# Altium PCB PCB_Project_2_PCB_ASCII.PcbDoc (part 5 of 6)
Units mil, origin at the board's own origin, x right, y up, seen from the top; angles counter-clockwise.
Board outline 3900 x 7800 mil, 6 copper layers (Top Layer, GND 1, Signal, Power, GND 2, Bottom Layer), stack 62.1 mil thick; 636 components, 334 nets, 1830 pads, 1401 vias.
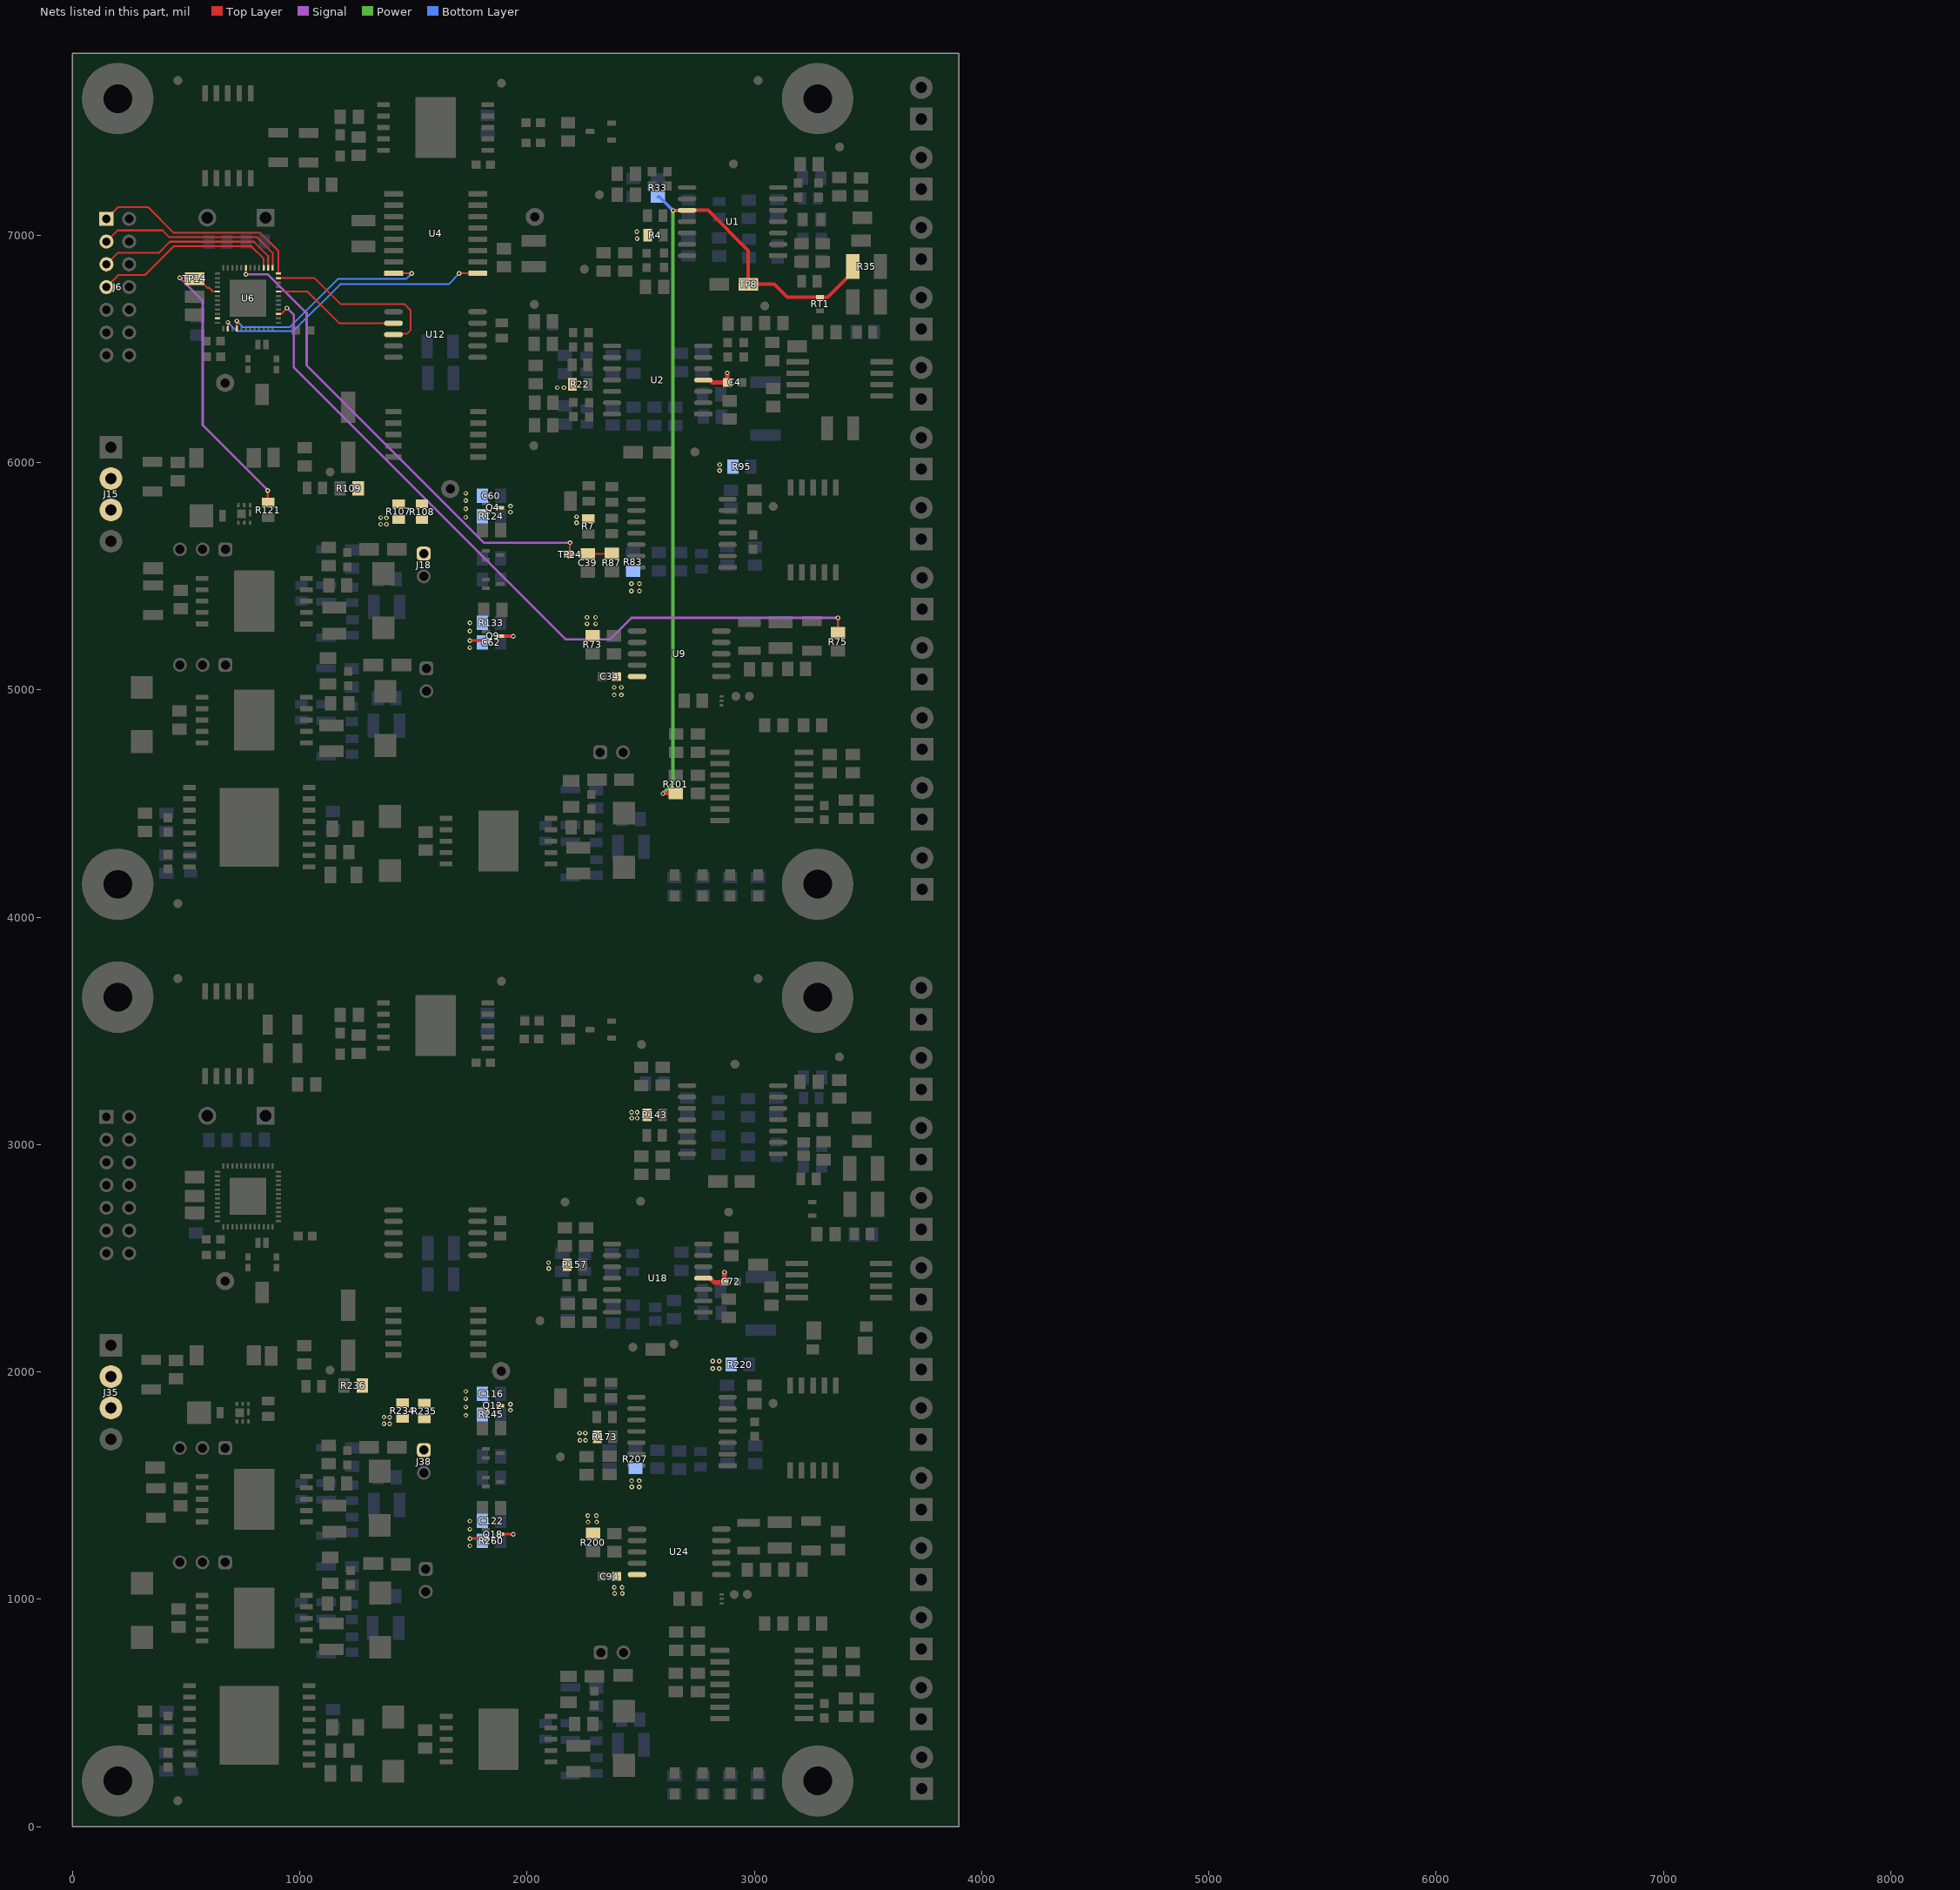
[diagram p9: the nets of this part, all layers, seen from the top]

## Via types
v1: diameter 20, hole 10, Top Layer to Bottom Layer, tented both sides, 1161 vias
v2: diameter 19.68, hole 7.87, Top Layer to Bottom Layer, 240 vias

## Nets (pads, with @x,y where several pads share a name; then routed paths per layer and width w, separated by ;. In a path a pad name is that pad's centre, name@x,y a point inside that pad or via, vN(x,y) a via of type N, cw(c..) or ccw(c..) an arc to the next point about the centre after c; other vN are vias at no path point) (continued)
"PWM for Boost": R121.2 TP14.1 U6.29 | length 1346.1
  Top Layer w8: v1(472.21,6812.48) TP14.1@536.72,6812.48 ; TP14.1@538.75,6807.64 548.11,6817.01 554.25,6810.87 554.25,6807.89 594.18,6767.96 602.45,6767.96 618.57,6751.84 U6.29@639.25,6751.84 ; R121.2@859.56,5826.44 v1(859.56,5876.24)
  Signal w10: v1(472.21,6812.48) 573.48,6711.22 573.48,6164.07 v1@862.25,5875.31
"PWM for Current Source": R75.1 U6.3 | length 3316.4
  Top Layer w8: U6.3@906.97,6653.42 907.69,6654.14 920.35,6654.14 944.33,6678.12 v1(944.33,6679.12) ; v1(3368,5316.59) 3368.41,5316.18 R75.1@3368.41,5250.84
  Signal w10: v1(944.33,6679.12) 975.12,6648.33 975.12,6417.77 2171.38,5221.51 2365.01,5221.51 2460.09,5316.59 v1(3368,5316.59)
"Servo Amp": C39.1 R87.2 TP24.1 U6.19 | length 2320.3
  Top Layer w8: U6.19@763.27,6856.18 763.35,6856.09 763.35,6827.42 v1(763.43,6827.34) ; v1@2189.25,5651.68 v1(2189.25,5647.41) TP24.1@2189.25,5595.74 2270.36,5595.74 2272.66,5598.04 2372.32,5598.04 R87.2@2373.79,5599.5
  Signal w10: v1@764.43,6827.64 859.66,6827.64 1030.94,6656.36 1030.94,6426.37 1810.31,5647 v1@2190,5647
SPI_CLK_3wire: U6.11 U12.8 | length 811
  Top Layer w7.5: U6.11@906.97,6810.9 1065.99,6810.9 1179.89,6697 1460.72,6697 1488.18,6669.54 1488.18,6581.18 1472.5,6565.5 1415.98,6565.5 U12.8@1413,6562.51
SPI_CLK_4wire: U4.16 U6.40 | length 984.7
  Top Layer w8: U6.40@723.73,6588.62 v1@723.73,6616.39 ; U4.16@1414.19,6831.75 v1@1493.41,6831.75
  Bottom Layer w7.5: v1(724,6622) 750.37,6595.63 956.66,6595.63 1169.03,6808 1470.03,6808 v1(1493.22,6831.19)
SPI_CS1: U4.1 U6.38 | length 1247.8
  Top Layer w8: v1(684.14,6616.44) 684.33,6616.25 684.33,6588.65 U6.38@684.53,6588.46 ; v1@1702.74,6831.57 U4.1@1783.7,6831.57
  Bottom Layer w7.5: v1(684.14,6616.44) 722.81,6577.78 972.61,6577.78 1178.94,6784.1 1655.28,6784.1 v1(1701.99,6830.81)
SPI_CS2: U6.8 U12.7 | length 563.7
  Top Layer w7.5: U6.8@906.97,6751.84 1034.22,6751.84 1173.55,6612.51 U12.7@1413,6612.51
SPI_CS3: U6.35
TCk: J6.7 U6.15 | length 829.1
  Top Layer w8: J6.7@150,6771.53 203.09,6824.62 320.19,6824.62 446.55,6950.98 787.4,6950.98 842.01,6896.37 U6.15@842.01,6856.18
TDI: J6.3 U6.13 | length 858.3
  Top Layer w8: J6.3@150,6971.53 199.14,7020.67 397.07,7020.67 427.23,6990.51 812.65,6990.51 881.38,6921.78 U6.13@881.38,6856.18
TDO: J6.1 U6.12 | length 957.7
  Top Layer w8: J6.1@150,7071.53 201.7,7123.23 332.99,7123.23 446.38,7009.84 826.88,7009.84 906.97,6929.75 U6.12@906.97,6830.58
"Temp Voltage": R33.1 R35.1 R101.2 RT1.2 TP8.1 U1.10 | length 3839.6
  Top Layer w10: R101.2@2654.22,4543.55 R101.2@2655.24,4544.57
  Top Layer w15: v1(2598.17,4543.55) R101.2@2654.22,4543.55 ; v1(2642.9,7108) U1.10@2707,7108 ; U1.10@2704.48,7109.19 2796.41,7109.19 2973.9,6931.7 TP8.1@2973.9,6784.12 3087.9,6784.12 3145.01,6727 RT1.2@3289,6727 3323.97,6727 3432.88,6835.91 R35.1@3432.88,6861.5
  Power w15: v1(2598.17,4543.55) 2642.9,4588.28 v1(2642.9,7108)
  Bottom Layer w15: R33.1@2577,7168.11 2583.5,7168.11 2642.9,7108.72 v1(2642.9,7108)
TMS: J6.5 U6.14 | length 830.5
  Top Layer w8: J6.5@150,6871.53 199.86,6921.39 380.52,6921.39 429.88,6970.75 798.73,6970.75 861.69,6907.79 U6.14@861.69,6856.18
Vcc: C4.2 C34.1 Q4.3 R73.2 R83.2 R95.2 U2.4 U9.10 | length 153.5
  Top Layer w20: U2.4@2775.45,6362.45 2805.58,6362.45 2816.03,6352 C4.2@2882.5,6352 2881.15,6353.35 v1(2881.15,6393.53)
  other v1: 2383.76,4977.57 2415.64,4977.57 2383.76,5010.35 2415.64,5010.35 2264,5290.09 2302,5290.09 2264,5318.53 2302,5318.53 2459.5,5434.63 2495.03,5434.63 2459.5,5466.58 2495.03,5466.58 1927.65,5781.6 1927.65,5808.04 2848.1,5964.52 2848.1,5990.07
Vcc(m): C72.2 C94.1 Q12.3 R200.2 R207.2 R220.2 U18.4 U24.10 | length 144.3
  Top Layer w20: U18.4@2775.84,2412.5 2805.97,2412.5 2824.47,2394 C72.2@2870,2394 ; v1(2868.5,2438.5) 2868.5,2399.18 C72.2@2870.7,2396.98
  other v1: 2385.58,1025.79 2419.93,1025.79 2384.21,1052.74 2418.57,1052.74 2268.84,1340.1 2306.84,1340.1 2267.51,1368.05 2305.51,1368.05 2461.13,1494.14 2493.74,1494.14 2460.44,1521.78 2493.65,1521.78 1927.65,1831.6 1927.65,1858.04 2817,2015 2846,2015 2817,2047 2846,2047
Vcc(m,x): J35.2 R234.1
  other v1: 1371.15,1771.93 1396.48,1771.93 1396.48,1800.21 1371.15,1800.97
Vcc(m,y): J38.1 R235.1
Vcc(mz): C116.1 Q12.2 R234.2 R235.2 R236.2 R245.2
  other v1: 1731,1808.84 1731,1845.92 1731,1882.2 1731,1914.19
Vcc(x): J15.2 R107.1
  other v1: 1356.59,5728.18 1381.92,5728.18 1381.92,5756.46 1356.59,5757.23
Vcc(y): J18.1 R108.1
Vcc(z): C60.1 Q4.2 R107.2 R108.2 R109.2 R124.2
  other v1: 1731,5758.84 1731,5795.92 1731,5832.2 1731,5864.19
Vee: Q9.3 R4.1 R7.1 R22.1 | length 57.7
  Top Layer w10: Q9.3@1882.44,5236.31 Q9.3@1882.75,5236 ; v1@1939.49,5236 v1(1939.88,5235.61)
  Top Layer w15: Q9.3@1882.75,5236 v1@1939.49,5236
  other v1: 2218.2,5734.8 2218.2,5761.07 2133.65,6329 2162.72,6329 2484.77,6984.53 2483.52,7014.5
Vee(m): Q18.3 R143.1 R157.1 R173.1 | length 55.8
  Top Layer w12: Q18.3@1882.44,1286.31 v1@1938.28,1286.31
  other v1: 1939.88,1285.61 2233,1699 2258,1699 2232,1731 2257,1731 2096,2455 2095,2481 2461,3116.19 2485,3116 2460.5,3142 2485,3142
Vee(mx): C122.2 J35.3 Q18.2 R260.1 | length 70.6
  Top Layer w12: v1@1747.18,1267.18 Q18.2@1817.74,1267.18
  other v1: 1748.89,1235 1748.89,1266.63 1748.89,1308.11 1748.89,1344.26
Vee(x): C62.2 J15.3 Q9.2 R133.1 | length 70.6
  Top Layer w12: v1(1748.89,5216.63) Q9.2@1819.44,5216.63
  other v1: 1748.89,5185 1748.89,5258.11 1748.89,5294.26
pads on no net: FID1.1 FID2.1 FID3.1 FID4.1 FID5.1 FID6.1 FID7.1 FID8.1 FID9.1 FID10.1 FID11.1 FID12.1 H1.1 H2.1 H3.1 H4.1 H5.1 H6.1 H7.1 H8.1 H9.0 H10.0 H11.0 H12.0 H13.0 H14.0 H15.0 H16.0 H17.0 H18.0 H19.0 H20.0 J6.2 J6.6 J6.10 J6.12 J6.13 J6.14 J27.2 J27.6 J27.10 J27.12 J27.13 J27.14 LBL1.0 Q2.1@2855.63,4972.34 Q2.2@2855.63,4951.67 Q2.3@2855.63,4931 Q3.0 Q11.1@2856.51,1022.55 Q11.2@2856.51,1001.88 Q11.3@2856.51,981.21 Q14.0 U6.1 U6.4 U6.5 U6.6 U6.7 U6.9 U6.10 U6.16 U6.17 U6.18 U6.25 U6.26 U6.27 U6.33 U6.34 U6.39 U6.42 U6.43 U6.49@719.17,6668.38 U6.49@719.17,6722.32 U6.49@719.17,6776.25 U6.49@773.11,6668.38 U6.49@773.11,6722.32 U6.49@773.11,6776.25 U6.49@827.04,6668.38 U6.49@827.04,6722.32 U6.49@827.04,6776.25 U7.7 U8.11@1530.37,7359.98 U8.11@1530.37,7405.25 U8.11@1530.37,7450.53 U8.11@1530.37,7495.81 U8.11@1530.37,7541.08 U8.11@1530.37,7586.36 U8.11@1575.64,7359.98 U8.11@1575.64,7405.25 U8.11@1575.64,7450.53 U8.11@1575.64,7495.81 U8.11@1575.64,7541.08 U8.11@1575.64,7586.36 U8.11@1620.92,7359.98 U8.11@1620.92,7405.25 U8.11@1620.92,7450.53 U8.11@1620.92,7495.81 U8.11@1620.92,7541.08 U8.11@1620.92,7586.36 U8.11@1666.19,7359.98 U8.11@1666.19,7405.25 U8.11@1666.19,7450.53 U8.11@1666.19,7495.81 U8.11@1666.19,7541.08 U8.11@1666.19,7586.36 U9.5 U9.6 U12.2 U12.3 U12.5 U12.6 U13.5 U13.11@732.16,4753.74 U13.11@732.16,4799.01 U13.11@732.16,4844.29 U13.11@732.16,4889.56 U13.11@732.16,4934.84 U13.11@732.16,4980.11 U13.11@777.43,4753.74 U13.11@777.43,4799.01 U13.11@777.43,4844.29 U13.11@777.43,4889.56 U13.11@777.43,4934.84 U13.11@777.43,4980.11 U13.11@822.71,4753.74 U13.11@822.71,4799.01 U13.11@822.71,4844.29 U13.11@822.71,4889.56 U13.11@822.71,4934.84 U13.11@822.71,4980.11 U13.11@867.99,4753.74 U13.11@867.99,4799.01 U13.11@867.99,4844.29 U13.11@867.99,4889.56 U13.11@867.99,4934.84 U13.11@867.99,4980.11 U15.5 U15.11@732.88,5276.9 U15.11@732.88,5322.17 U15.11@732.88,5367.45 U15.11@732.88,5412.72 U15.11@732.88,5458 U15.11@732.88,5503.28 U15.11@778.15,5276.9 U15.11@778.15,5322.17 U15.11@778.15,5367.45 U15.11@778.15,5412.72 U15.11@778.15,5458 U15.11@778.15,5503.28 U15.11@823.43,5276.9 U15.11@823.43,5322.17 U15.11@823.43,5367.45 U15.11@823.43,5412.72 U15.11@823.43,5458 U15.11@823.43,5503.28 U15.11@868.7,5276.9 U15.11@868.7,5322.17 U15.11@868.7,5367.45 U15.11@868.7,5412.72 U15.11@868.7,5458 U15.11@868.7,5503.28 U16.5 U16.11@1807,4221.49 U16.11@1807,4266.77 U16.11@1807,4312.04 U16.11@1807,4357.32 U16.11@1807,4402.59 U16.11@1807,4447.87 U16.11@1852.28,4221.49 U16.11@1852.28,4266.77 U16.11@1852.28,4312.04 U16.11@1852.28,4357.32 U16.11@1852.28,4402.59 U16.11@1852.28,4447.87 U16.11@1897.56,4221.49 U16.11@1897.56,4266.77 U16.11@1897.56,4312.04 U16.11@1897.56,4357.32 U16.11@1897.56,4402.59 U16.11@1897.56,4447.87 U16.11@1942.83,4221.49 U16.11@1942.83,4266.77 U16.11@1942.83,4312.04 U16.11@1942.83,4357.32 U16.11@1942.83,4402.59 U16.11@1942.83,4447.87 U20.9 U20.10 U20.25 U20.26 U20.27 U20.33 U20.34 U20.39 U20.42 U20.43 U20.49@719.17,2718.38 U20.49@719.17,2772.32 U20.49@719.17,2826.25 U20.49@773.11,2718.38 U20.49@773.11,2772.32 U20.49@773.11,2826.25 U20.49@827.04,2718.38 U20.49@827.04,2772.32 U20.49@827.04,2826.25 U22.7 U23.11@1530.37,3409.98 U23.11@1530.37,3455.25 U23.11@1530.37,3500.53 U23.11@1530.37,3545.8 U23.11@1530.37,3591.08 U23.11@1530.37,3636.36 U23.11@1575.64,3409.98 U23.11@1575.64,3455.25 U23.11@1575.64,3500.53 U23.11@1575.64,3545.8 U23.11@1575.64,3591.08 U23.11@1575.64,3636.36 U23.11@1620.92,3409.98 U23.11@1620.92,3455.25 U23.11@1620.92,3500.53 U23.11@1620.92,3545.8 U23.11@1620.92,3591.08 U23.11@1620.92,3636.36 U23.11@1666.19,3409.98 U23.11@1666.19,3455.25 U23.11@1666.19,3500.53 U23.11@1666.19,3545.8 U23.11@1666.19,3591.08 U23.11@1666.19,3636.36 U24.5 U24.6 U27.2 U27.3 U27.5 U27.6 U28.5 U28.11@732.16,803.74 U28.11@732.16,849.01 U28.11@732.16,894.29 U28.11@732.16,939.56 U28.11@732.16,984.84 U28.11@732.16,1030.11 U28.11@777.43,803.74 U28.11@777.43,849.01 U28.11@777.43,894.29 U28.11@777.43,939.56 U28.11@777.43,984.84 U28.11@777.43,1030.11 U28.11@822.71,803.74 U28.11@822.71,849.01 U28.11@822.71,894.29 U28.11@822.71,939.56 U28.11@822.71,984.84 U28.11@822.71,1030.11 U28.11@867.99,803.74 U28.11@867.99,849.01 U28.11@867.99,894.29 U28.11@867.99,939.56 U28.11@867.99,984.84 U28.11@867.99,1030.11 U30.5 U30.11@732.88,1326.9 U30.11@732.88,1372.17 U30.11@732.88,1417.45 U30.11@732.88,1462.72 U30.11@732.88,1508 U30.11@732.88,1553.28 U30.11@778.15,1326.9 U30.11@778.15,1372.17 U30.11@778.15,1417.45 U30.11@778.15,1462.72 U30.11@778.15,1508 U30.11@778.15,1553.28 U30.11@823.43,1326.9 U30.11@823.43,1372.17 U30.11@823.43,1417.45 U30.11@823.43,1462.72 U30.11@823.43,1508 U30.11@823.43,1553.28 U30.11@868.7,1326.9 U30.11@868.7,1372.17 U30.11@868.7,1417.45 U30.11@868.7,1462.72 U30.11@868.7,1508 U30.11@868.7,1553.28 U31.5 U31.11@1807.06,271.49 U31.11@1807.06,316.77 U31.11@1807.06,362.04 U31.11@1807.06,407.32 U31.11@1807.06,452.59 U31.11@1807.06,497.87 U31.11@1852.34,271.49 U31.11@1852.34,316.77 U31.11@1852.34,362.04 U31.11@1852.34,407.32 U31.11@1852.34,452.59 U31.11@1852.34,497.87 U31.11@1897.61,271.49 U31.11@1897.61,316.77 U31.11@1897.61,362.04 U31.11@1897.61,407.32 U31.11@1897.61,452.59 U31.11@1897.61,497.87 U31.11@1942.89,271.49 U31.11@1942.89,316.77 U31.11@1942.89,362.04 U31.11@1942.89,407.32 U31.11@1942.89,452.59 U31.11@1942.89,497.87
copper on no net:
  other v1: 2778.82,5945.11

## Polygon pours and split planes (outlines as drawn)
GND on Top Layer "GND-GND" (solid, pour order 1158): 12.86,7692.78 12.86,4052.5 96.94,3968.42 3774.01,3968.42 3875.54,4069.96 3875.54,7746.23 3830.41,7791.36 111.44,7791.36
GND on Top Layer "Top Layer-GND(m) 1" (solid, pour order 1160): 1367.89,6251.59 1367.89,6068.25 1377.47,6058.67 1476.78,6058.67 1533.18,6002.28 1823.62,6002.28 1839.09,6017.75 1839.09,6244.32 1808.65,6274.76 1391.06,6274.76
NetC42_1 on Top Layer "Top Layer-NetC42_1" (solid, pour order 488): 18 vertices, not listed, extent 1076.36,5841.48 1448,6098
Vcc(z) on Top Layer "Top Layer-Vcc(z)" (solid, pour order 480): 20 vertices, not listed, extent 1227.91,5743.24 1842.76,5932.18
GND on Top Layer "Top Layer-GND 21" (solid, pour order 404): 3274.08,4445.15 3280.15,4451.22 3331.98,4451.22 3335.27,4447.93 3335.27,4413.01 3335.27,4368.28 3329.64,4362.66 3280.56,4362.66 3274.08,4369.14
GND on Top Layer "Top Layer-GND 22" (solid, pour order 406): 2346.3,5296.2 2363.14,5313.04 2402.95,5313.04 2420.09,5295.9 2420.09,5213.22 2412.24,5205.38 2352.16,5205.38 2346.3,5211.24
GND on Top Layer "Top Layer-GND 23" (solid, pour order 408): 1105.95,6604.76 1099.28,6611.44 1030.17,6611.44 1024.08,6605.35 1024.08,6559.03 1031.95,6551.16 1099.43,6551.16 1105.95,6557.68
P3V3 on Top Layer "Top Layer-P3V3 3" (solid, pour order 410): 877.89,6602.13 886.58,6602.13 897.27,6591.44 951.59,6591.44 965.76,6605.6 997.4,6605.6 1007.88,6595.12 1007.88,6547.67 977.9,6517.69 903.56,6517.69 875.15,6546.1 875.15,6599.39
GND on Top Layer "Top Layer-GND 24" (solid, pour order 412): 746.39,6420.35 756.49,6430.45 921.16,6430.45 937.2,6414.42 937.2,6260.71 912.75,6236.26 773.27,6236.26 746.39,6263.14
Vee on Top Layer "Top Layer-Vee 2" (solid, pour order 420): 2456.28,7022.47 2465.75,7031.95 2549.37,7031.95 2556.27,7025.05 2556.27,6973.77 2550.54,6968.05 2471.76,6968.05 2456.27,6983.53
Vee on Top Layer "Top Layer-Vee" (solid, pour order 422): 2215.17,6376.04 2224.09,6367.12 2224.09,6318 2212.09,6306 2133.65,6306 2119,6320.65 2119,6365.39 2129.65,6376.04
GND on Top Layer "Top Layer-GND 19" (solid, pour order 426): 3357.67,4451.93 3357.67,4372.64 3373.94,4356.66 3428.21,4356.66 3445.76,4374.21 3445.76,4457.29 3438.23,4464.82 3370.55,4464.82
P5V0 on Top Layer "Top Layer-P5V0" (solid, pour order 430): 3174,4541 3174,4518 3181,4511 3248.03,4511 3292.03,4467 3345.73,4467 3359.14,4480.41 3359.14,4528.86 3338,4550 3184,4550 3173,4539
P5V0 on Top Layer "Top Layer-P5V0 5" (solid, pour order 432): 2945.5,4871.21 2945.5,4808.82 2958.2,4796.11 3070.29,4796.11 3084.45,4810.27 3084.45,4871.72 3071.57,4884.6 2958.88,4884.6
GND on Top Layer "Top Layer-GND 18" (solid, pour order 434): 2792.87,4864.75 2778.02,4879.6 2732.95,4879.6 2716.18,4862.83 2716.18,4842.83 2716.18,4784.53 2727.83,4772.87 2783.33,4772.87 2792.87,4782.41
GND on Top Layer "Top Layer-GND 17" (solid, pour order 436): 2711.35,4562.38 2719.81,4570.84 2780.1,4570.84 2801.84,4549.1 2889.88,4549.1 2897.97,4541.01 2897.97,4519.88 2888.99,4510.91 2807.49,4510.91 2783.22,4486.64 2717.87,4486.64 2711.35,4493.16
Vcc on Top Layer "Top Layer-Vcc" (solid, pour order 438): 1872.72,5822.72 1934.09,5822.72 1940,5816.82 1940,5773 1933.86,5766.86 1871.47,5766.86 1859,5779.33 1859,5809
GND on Top Layer "Top Layer-GND 1" (solid, pour order 440): 2241.2,5082.32 2252.23,5093.35 2344.94,5093.35 2355.19,5083.1 2355.19,5038.02 2344.15,5026.98 2249.38,5026.98 2241.2,5035.16
P3V3 on Top Layer "Top Layer-P3V3 2" (solid, pour order 442): 1300.6,7390.12 1161.98,7390.12 1151.39,7379.54 1151.39,7291 1162.59,7279.8 1389.79,7279.8 1400.86,7290.87 1400.86,7381.58 1392.32,7390.12
GND on Top Layer "Top Layer-GND 16" (solid, pour order 444): 21 vertices, not listed, extent 1335.38,7279.36 1860.83,7611.74
P3V3 on Top Layer "Top Layer-P3V3" (solid, pour order 446): 1816.08,7286.42 1823.74,7278.76 1886.39,7278.76 1896.07,7288.44 1896.07,7378.12 1882.61,7391.58 1802.16,7391.58 1797.01,7386.42 1797.01,7357.92 1816.08,7338.85
GND on Top Layer "Top Layer-GND 2" (solid, pour order 450): 651.86,6618.05 651.97,6611.16 647.59,6606.78 638.03,6606.78 613.23,6581.99 613.23,6447.78 606.79,6441.35 502.54,6441.34 496.4,6447.48 496.4,6575.06 511.83,6590.49 580.53,6590.49 610.97,6620.92 648.99,6620.92
GND on Top Layer "Top Layer-GND 17" (solid, pour order 452): 2970.79,5641.66 2962.61,5633.48 2962.61,5592.42 2968.05,5586.98 3073.44,5586.98 3080.41,5593.95 3080.41,5634.4 3073.16,5641.66
P5V0(Op) on Top Layer "Top Layer-P5V0(Op) 2" (solid, pour order 456): 3139,7085 3150,7074 3150,7039 3139.11,7028.11 3026.89,7028.11 3017,7038 3017,7077 3025,7085
P5V0(Op) on Top Layer "Top Layer-P5V0(Op) 1" (solid, pour order 460): 2979.89,5716.35 3094.86,5716.35 3108.04,5703.17 3108.04,5666.05 3098.78,5656.79 2975.87,5656.79 2965.48,5667.19 2842.1,5667.19 2835.49,5673.8 2835.49,5693.09 2845.05,5702.65 2966.19,5702.65
Vcc on Top Layer "Top Layer-Vcc 2" (solid, pour order 464): 2235,5221.03 2251.94,5204.1 2318.39,5204.1 2328.37,5214.08 2328.37,5318.48 2310.99,5335.86 2252.33,5335.86 2235,5318.53
Vcc on Top Layer "Top Layer-Vcc 3" (solid, pour order 466): 2370.99,5077.36 2370.99,4968.49 2380.85,4958.63 2418.85,4958.63 2431.28,4971.06 2431.28,5029.08 2439.38,5037.18 2517.36,5037.18 2531.27,5051.08 2531.27,5076.9 2521.5,5086.67 2380.31,5086.67
P5V0(R) on Top Layer "Top Layer-P5V0(R)" (solid, pour order 470): 1738,6481 1831.98,6481 1846,6466.98 1846,6376.04 1833.82,6363.86 1746.06,6363.86 1728,6381.92 1728,6471
GND on Top Layer "Top Layer-GND 3" (solid, pour order 472): 1458.05,6481 1474.93,6464.12 1474.93,6399.39 1460.48,6384.94 1373.4,6384.94 1354.3,6404.05 1354.3,6462.51 1372,6480.22 1372,6481
GND on Top Layer "Top Layer-GND 4" (solid, pour order 474): 1454,7052 1462,7044 1462,7022.73 1454.27,7015 1238.44,7015 1213.44,7040 1213.44,7128.53 1239.91,7155 1326.91,7155 1347.96,7133.95 1347.96,7062.2 1358.16,7052
GND on Top Layer "Top Layer-GND 5" (solid, pour order 476): 17 vertices, not listed, extent 1728,6914 2091,7131.57
P5V0(R) on Top Layer "Top Layer-P5V0(R) 1" (solid, pour order 478): 2146.94,6897 2161,6882.94 2161,6807.45 2150.49,6796.94 1880.56,6796.94 1859,6818.5 1859,6849 1847.01,6860.99 1737.56,6860.99 1728,6870.55 1728,6887 1738,6897
GND on Top Layer "Top Layer-GND 6" (solid, pour order 482): 1244,6376 1258.63,6361.37 1258.63,6177.7 1244.59,6163.66 1178.48,6163.66 1161,6181.14 1161,6356.67 1180.33,6376
GND on Top Layer "Top Layer-GND 7" (solid, pour order 484): 1059.02,6035 1072.98,6048.95 1072.98,6150.35 1064.28,6159.04 970,6159.04 956.88,6145.92 956.88,6047.89 969.77,6035
Vcc(x) on Top Layer "Top Layer-Vcc(x)" (solid, pour order 490): 1460.05,5776.57 1469.96,5766.66 1469.96,5721.13 1455.75,5706.92 1351.3,5706.92 1339.36,5718.86 1339.36,5765.3 1350.63,5776.57
P5V0(R) on Top Layer "Top Layer-P5V0(R) 2" (solid, pour order 492): 931.88,5953.55 944.13,5941.29 974.54,5941.29 992.28,5923.56 992.28,5859.85 1001.54,5850.59 1051.51,5850.59 1059.76,5858.84 1059.76,6009.12 1049.66,6019.21 945.98,6019.21 931.88,6005.1
GND on Top Layer "Top Layer-GND 8" (solid, pour order 494): 823,5830.41 814.53,5838.88 786.57,5838.88 775.84,5828.15 775.84,5763.21 779.61,5759.44 794.44,5759.44 823,5788
GND on Top Layer "Top Layer-GND 9" (solid, pour order 496): 1191.52,4152.24 1212.77,4131 1281.51,4131 1304.01,4153.5 1304.01,4412.79 1284.54,4432.26 1207.05,4432.26 1191.53,4416.74
GND on Top Layer "Top Layer-GND 10" (solid, pour order 498): 380.37,4412.5 363.86,4429.01 257.08,4429.01 243.63,4442.46 243.63,4507.68 263.84,4527.9 432.72,4527.9 448,4512.62 448,4421 439.5,4412.5
GND on Top Layer "Top Layer-GND 11" (solid, pour order 500): 383.56,4234 549.44,4234 559,4224.44 559,4153.5 536.5,4131 388.35,4131 365.85,4153.5 365.85,4216.29
P5V0 on Top Layer "Top Layer-P5V0 2" (solid, pour order 502): 470,4419 470,4520.64 446.12,4544.52 392.15,4544.52 374.92,4561.76 374.92,4609.55 390.74,4625.38 551.8,4625.38 569.75,4607.43 569.75,4419.94 552.57,4402.76 486.24,4402.76
P5V0(Op) on Top Layer "Top Layer-P5V0(Op)" (solid, pour order 504): 23 vertices, not listed, extent 991.04,4270.75 1683,4587.32
NetQ3_3 on Top Layer "Top Layer-NetQ3_3" (solid, pour order 506): 776.07,5724.86 781.37,5719.57 888.43,5719.57 898,5729.13 898,5773 891.83,5779.17 836.17,5779.17 803,5746 778.73,5746 776.07,5743.34
NetR134_1 on Top Layer "Top Layer-NetR134_1" (solid, pour order 516): 2345,4643 2357,4631 2357,4539 2334.82,4516.82 2258.18,4516.82 2215,4560 2153,4560 2137,4576 2137,4630 2150,4643
GND on Top Layer "Top Layer-GND(m)" (solid, pour order 522): 32 vertices, not listed, extent 1337,4139.61 2513.1,4488.59
P5V0 on Top Layer "Top Layer-P5V0 4" (solid, pour order 524): 20 vertices, not listed, extent 238.81,4799.99 606,5148.06
NetR111_1 on Top Layer "Top Layer-NetR111_1" (solid, pour order 528): 1081,5169.07 1081,5117 1090,5108 1143.4,5108 1190.9,5060.5 1358.87,5060.5 1373,5074.62 1373,5162.79 1351.25,5184.54 1096.48,5184.54
GND on Top Layer "Top Layer-GND 14" (solid, pour order 534): 32 vertices, not listed, extent 249.88,4678.1 1436.97,5018
NetR117_1 on Top Layer "Top Layer-NetR117_1" (solid, pour order 536): 1089.07,5660.51 1089.07,5608.45 1098.51,5599.01 1167.33,5599.01 1185.35,5581 1348,5581 1356,5589 1356,5659 1344.04,5670.96 1099.52,5670.96
GND on Top Layer "Top Layer-GND 15" (solid, pour order 540): 32 vertices, not listed, extent 300.46,5204.1 1438.97,5544
NetC56_1 on Top Layer "Top Layer-NetC56_1" (solid, pour order 546): 25 vertices, not listed, extent 289.15,5324.03 623.51,5829.32
Vee on Top Layer "Top Layer-Vee 1" (solid, pour order 416): 2206.02,5778.61 2194.9,5767.49 2194.9,5734.73 2208.83,5720.79 2287.76,5720.79 2299.32,5732.35 2299.32,5772.69 2293.39,5778.61
NetC63_1 on Top Layer "Top Layer-NetC63_1" (solid, pour order 520): 25 vertices, not listed, extent 2057.08,4219.34 2484.63,4766
NetC44_1 on Top Layer "Top Layer-NetC44_1" (solid, pour order 526): 29 vertices, not listed, extent 982.23,4754 1602.23,5145.06
NetC51_1 on Top Layer "Top Layer-NetC51_1" (solid, pour order 542): 29 vertices, not listed, extent 970,5274 1590,5660.39
NetR96_2 on Top Layer "Top Layer-NetR96_2" (solid, pour order 716): 3394.46,5489.26 3375.2,5470 3147.62,5470 3133.85,5483.77 3133.85,5797.85 3195.57,5859.57 3195.57,5918.78 3206.23,5929.44 3376.5,5929.44 3394.46,5911.48
P3V3 on Top Layer "Top Layer-P3V3 1" (solid, pour order 448): 629.07,6553.95 655.08,6579.97 655.08,6598.78 659.1,6602.79 668.54,6602.79 671.68,6599.65 671.68,6571.77 682.51,6560.94 719.01,6560.94 740.2,6539.75 740.2,6451.97 728.26,6440.04 633.97,6440.04 629.07,6444.94
NetC111_1 on Top Layer "Top Layer-NetC51_1" (solid, pour order 818): 27 vertices, not listed, extent 978.69,1324 1590,1710.39
NetC120_1 on Top Layer "Top Layer-NetC56_1" (solid, pour order 820): 25 vertices, not listed, extent 298.67,1374.03 615.11,1888.9
GND(m) on Top Layer "Top Layer-GND 15" (solid, pour order 824): 32 vertices, not listed, extent 300.46,1254.1 1438.97,1594
NetR244_1 on Top Layer "Top Layer-NetR117_1" (solid, pour order 828): 1087.72,1709.16 1087.72,1655.22 1094.9,1648.04 1168.3,1648.04 1185.35,1631 1348,1631 1356,1639 1356,1709 1344.04,1720.96 1099.52,1720.96
NetQ14_3 on Top Layer "Top Layer-NetQ3_3" (solid, pour order 836): 768.68,1773.31 772.42,1769.57 888.43,1769.57 898,1779.13 898,1823 891.83,1829.17 836.17,1829.17 803,1796 774.73,1796 768.68,1789.95
GND(m) on Top Layer "Top Layer-GND 8" (solid, pour order 838): 818.45,1875.72 809.98,1884.19 782.02,1884.19 769.45,1871.62 769.45,1808.31 771.45,1806.31 791.45,1806.31 818.45,1833.31
GND(m) on Top Layer "Top Layer-GND 14" (solid, pour order 842): 32 vertices, not listed, extent 248.61,728.1 1436.97,1068
NetR238_1 on Top Layer "Top Layer-NetR111_1" (solid, pour order 848): 1081,1219.07 1081,1167 1094.12,1153.88 1147.52,1153.88 1197.33,1104.06 1352.44,1104.06 1373,1124.62 1373,1212.79 1351.25,1234.54 1096.48,1234.54
P5V0(m) on Top Layer "Top Layer-P5V0 4" (solid, pour order 850): 19 vertices, not listed, extent 239.45,849.99 606,1200.64
Vcc(m,y) on Top Layer "Top Layer-Vcc(y)" (solid, pour order 856): 1509.17,1704.88 1509.17,1808.51 1518.7,1818.03 1580.44,1818.03 1589.49,1808.98 1589.49,1635.46 1570.64,1616.61 1520.6,1616.61 1509.17,1628.04
Vcc(m) on Top Layer "Top Layer-Vcc" (solid, pour order 858): 1866.72,1870.57 1931.94,1870.57 1940.71,1861.8 1940.71,1823.71 1933.46,1816.47 1871.86,1816.46 1859.98,1828.34 1859.98,1863.83
Vcc(mz) on Top Layer "Top Layer-Vcc(z)" (solid, pour order 860): 17 vertices, not listed, extent 1246.22,1791.09 1841.49,1984.62
GND(m) on Top Layer "Top Layer-GND 9" (solid, pour order 864): 1191.27,201.79 1212.51,180.55 1281.26,180.55 1303.76,203.05 1303.76,462.34 1284.28,481.81 1206.8,481.81 1191.27,466.28
GND(m) on Top Layer "Top Layer-GND 10" (solid, pour order 866): 380.12,462.05 364.71,477.45 256.04,477.45 242.41,491.08 242.41,562.43 257.42,577.44 432.47,577.44 447.75,562.17 447.74,470.55 439.24,462.05
GND(m) on Top Layer "Top Layer-GND 11" (solid, pour order 868): 391.47,287.92 544.81,287.92 558.75,273.99 558.74,203.05 536.24,180.55 388.09,180.55 375.47,193.17 375.47,271.92
P5V0(m,Op) on Top Layer "Top Layer-P5V0(Op)" (solid, pour order 872): 23 vertices, not listed, extent 990.78,320.29 1682.75,636.87
GND(m) on Top Layer "Top Layer-GND(m)" (solid, pour order 878): 31 vertices, not listed, extent 1336.74,183.98 2512.84,538.14
NetC123_1 on Top Layer "Top Layer-NetC63_1" (solid, pour order 880): 23 vertices, not listed, extent 2063.39,268.88 2484.38,815.55
P5V0(mR) on Top Layer "Top Layer-P5V0(R) 2" (solid, pour order 882): 1046.2,2068.28 936.73,2068.28 924.48,2056.03 924.48,1989.97 935.65,1978.8 971.89,1978.8 986.92,1963.77 986.92,1913.36 1002.69,1897.59 1041.78,1897.59 1053.63,1909.44 1053.63,2060.85
NetC102_1 on Top Layer "Top Layer-NetC42_1" (solid, pour order 884): 1453.62,2057.69 1446,2050.07 1300.42,2050.07 1225.47,1975.12 1225.47,1902.26 1211.69,1888.48 1087.01,1888.48 1072.23,1903.26 1072.23,2039.18 1178.05,2145 1305,2145 1357,2093 1444.18,2093 1453.62,2083.56
GND(m) on Top Layer "Top Layer-GND 7" (solid, pour order 886): 1056.64,2086.54 1071.98,2101.87 1071.98,2197.35 1063.28,2206.04 969,2206.04 955.88,2192.92 955.88,2104.37 973.71,2086.54
GND(m) on Top Layer "Top Layer-GND 6" (solid, pour order 888): 1243,2423 1257.63,2408.37 1257.63,2224.7 1243.59,2210.66 1177.48,2210.66 1160,2228.14 1160,2403.67 1179.33,2423
P5V0(mR) on Top Layer "Top Layer-P5V0(R)" (solid, pour order 892): 1737,2528 1830.98,2528 1845,2513.98 1845,2423.04 1833.91,2411.94 1743.97,2411.94 1727,2428.92 1727,2518
P3V3(m) on Top Layer "Top Layer-P3V3 2" (solid, pour order 926): 1300.5,3440.08 1161.88,3440.08 1151.29,3429.5 1151.29,3352.19 1168.69,3334.8 1380.54,3334.8 1401.96,3356.21 1401.96,3433.7 1395.57,3440.08
GND(m) on Top Layer "Top Layer-GND 16" (solid, pour order 928): 21 vertices, not listed, extent 1337.95,3332.96 1860.74,3669.58
P3V3(m) on Top Layer "Top Layer-P3V3" (solid, pour order 930): 1816.52,3327.93 1831.36,3313.09 1877.63,3313.09 1896.22,3331.69 1896.22,3427.83 1885.91,3438.14 1803.66,3438.14 1796.91,3431.39 1796.91,3407.88 1816.52,3388.27
P3V3(mb) on Top Layer "Top Layer-P3V3(mb)" (solid, pour order 932): 1050.58,3225.21 1040.03,3235.76 1040.03,3294.72 1047.91,3302.59 1164.86,3302.59 1175.99,3291.47 1175.99,3234.45 1166.75,3225.21
P2V5 on Top Layer "Top Layer-P2V5" (solid, pour order 934): 21 vertices, not listed, extent 768.23,3163.77 1024.24,3576.09
GND(m) on Top Layer "Top Layer-GND" (solid, pour order 936): 18 vertices, not listed, extent 547.6,3250.23 893.88,3722.06
GND(m) on Top Layer "Top Layer-GND 23" (solid, pour order 942): 1122.65,2618.91 1116.79,2624.77 1036.66,2624.77 1030.57,2618.68 1030.57,2572.36 1038.45,2564.49 1119.09,2564.49 1122.65,2568.05
GND(m) on Top Layer "Top Layer-GND 24" (solid, pour order 946): 718.39,2463.04 735.84,2480.49 921.28,2480.49 937.32,2464.45 937.32,2250.11 917.83,2230.62 725.91,2230.62 718.39,2238.14
GND(m) on Top Layer "Top Layer-GND 2" (solid, pour order 948): 652.06,2668.53 652.19,2659.95 650.04,2657.8 641.01,2657.8 613.75,2630.53 613.75,2496.33 604.36,2486.94 506.01,2486.94 496.92,2496.03 496.92,2580.89 535.23,2619.19 564.96,2619.19 616.33,2670.56 650.03,2670.56
P3V3(m) on Top Layer "Top Layer-P3V3 1" (solid, pour order 950): 629.67,2601.95 656.79,2629.08 656.79,2650.65 659.42,2653.28 668.86,2653.28 671.49,2650.65 671.49,2624.23 681.69,2614.03 719.61,2614.03 739.01,2594.62 739.01,2509.25 719.23,2489.47 635.24,2489.47 629.67,2495.04
GND(m) on Top Layer "Top Layer-GND 21" (solid, pour order 952): 3278.51,494.33 3283.97,499.79 3329.86,499.79 3333.87,495.77 3333.87,460.85 3333.87,416.13 3328.25,410.5 3286.95,410.5 3278.51,418.95
GND(m) on Top Layer "Top Layer-GND 19" (solid, pour order 954): 3365.19,510.31 3365.19,423.73 3379,410.16 3430.02,410.16 3441.71,421.85 3441.71,508.29 3433.76,516.24 3371.12,516.24
GND(m) on Top Layer "Top Layer-GND 20" (solid, pour order 956): 3279.23,947.7 3264.58,933.05 3264.58,863.24 3290.34,837.49 3290.34,745.2 3299.73,735.81 3364.68,735.81 3378.35,749.47 3378.35,931.14 3361.78,947.7
P5V0(m) on Top Layer "Top Layer-P5V0" (solid, pour order 958): 3172.61,588.84 3172.61,565.84 3179.61,558.84 3248.97,558.84 3292.26,515.55 3343.86,515.55 3357.75,529.44 3357.75,576.7 3336.61,597.84 3182.61,597.84 3171.61,586.84
P5V0(m) on Top Layer "Top Layer-P5V0 5" (solid, pour order 960): 2944.1,919.06 2944.1,856.66 2956.81,843.96 3068.9,843.96 3083.06,858.11 3083.06,918.73 3065.77,936.02 2961.06,936.02
GND(m) on Top Layer "Top Layer-GND 18" (solid, pour order 962): 2791.47,912.59 2776.62,927.44 2731.55,927.44 2714.79,910.67 2714.79,890.67 2714.79,832.37 2726.44,820.71 2781.94,820.71 2791.47,830.25
GND(m) on Top Layer "Top Layer-GND 17" (solid, pour order 964): 2709.96,614.11 2718.01,622.16 2782.81,622.16 2808.03,596.94 2888.48,596.94 2896.57,588.85 2896.57,567.73 2887.6,558.75 2806.1,558.75 2781.83,534.49 2716.48,534.49 2709.96,541.01
GND(m) on Top Layer "Top Layer-GND 22" (solid, pour order 966): 2349.22,1346.11 2363.23,1360.12 2407.22,1360.12 2422.46,1344.88 2422.46,1263.37 2415.51,1256.41 2356.73,1256.41 2349.22,1263.92
GND(m) on Top Layer "Top Layer-GND 1" (solid, pour order 968): 2352.07,1080.07 2342.62,1070.62 2248.15,1070.62 2241.08,1077.69 2241.08,1123.99 2250.3,1133.21 2340.9,1133.21 2352.07,1122.04
Vcc(m) on Top Layer "Top Layer-Vcc 2" (solid, pour order 970): 2246.36,1266.99 2257.7,1255.64 2318.29,1255.64 2329.15,1266.51 2329.15,1368.3 2313.36,1384.09 2261.12,1384.09 2246.36,1369.33
Vcc(m) on Top Layer "Top Layer-Vcc 3" (solid, pour order 972): 2371.56,1120.46 2371.56,1015.52 2382.68,1004.4 2423.2,1004.4 2435.29,1016.49 2435.29,1076.85 2446.76,1088.32 2531.51,1088.32 2545.37,1102.79 2545.37,1117.77 2532.94,1130.19 2381.3,1130.19
P3V3(m) on Top Layer "Top Layer-P3V3(m)" (solid, pour order 1056): 877.48,2650.27 889.03,2650.27 914.52,2624.77 1009.47,2624.77 1016.14,2618.1 1016.14,2571.66 1001.31,2556.83 908.75,2556.83 873.19,2592.39 873.19,2645.98
GND(m) on Top Layer "Top Layer-GND 3" (solid, pour order 890): 1374.83,2528 1459.53,2528 1474.34,2513.19 1474.34,2454.55 1457.39,2437.6 1378.02,2437.6 1363.02,2452.6 1363.02,2516.19
NetR221_2 on Top Layer "Top Layer-NetR96_2" (solid, pour order 1074): 3392.31,1540 3373.05,1520.74 3145.47,1520.74 3131.7,1534.51 3131.7,1848.59 3194.04,1910.93 3194.04,1970.23 3204.42,1980.61 3373.91,1980.61 3392.31,1962.22
GND(m) on Top Layer "Top Layer-GND(m) 1" (solid, pour order 1076): 1367.49,2283.84 1367.49,2118.65 1377.47,2108.67 1476.78,2108.67 1533.17,2052.28 1823.62,2052.28 1839.09,2067.75 1839.09,2294.32 1808.65,2324.76 1391.06,2324.76 1367.89,2301.59
Vcc(m,x) on Top Layer "Top Layer-Vcc(m,x)" (solid, pour order 1086): 1369.91,1816.47 1482.5,1816.47 1487.12,1811.85 1487.11,1766.76 1478.27,1757.92 1365.51,1757.92 1357.11,1766.32 1357.11,1803.66
Vee(m) on Top Layer "Top Layer-Vee(m) 2" (solid, pour order 1092): 2545.84,3169.39 2554,3161.23 2554,3101 2546,3093 2461.5,3093 2445,3109.5 2445,3155.91 2458.48,3169.39
Vee(m) on Top Layer "Top Layer-Vee(m) 1" (solid, pour order 1094): 2190.09,2509.52 2203,2496.62 2203,2440.76 2193.24,2431 2091,2431 2074,2448 2074,2493.35 2090.18,2509.52
Vee(m) on Top Layer "Top Layer-Vee(m)" (solid, pour order 1096): 2324.55,1748.45 2334,1739 2334,1687 2327.18,1680.18 2226.67,1680.18 2218,1688.85 2218,1740.42 2226.03,1748.45
GND(m) on Top Layer "Top Layer-GND(m) 2" (solid, pour order 1106): 2325.64,1837.14 2334.03,1828.75 2334.03,1773.15 2326.05,1765.16 2224.51,1765.16 2213,1776.68 2213,1826.88 2223.26,1837.14
NetD8_2 on Top Layer "Top Layer-NetD8_2" (solid, pour order 1114): 905.59,6079.66 778.54,6079.5 747.77,6048.74 747.77,5920.97 642.27,5815.47 642.27,5732.78 652.77,5722.28 759.31,5722.28 762.33,5725.31 762.33,5858.64 868.41,5964.73 906.52,5964.73 916.11,5974.32 916.11,6069.14
GND on Top Layer "Top Layer-GND 12" (solid, pour order 1116): 489.85,5953.76 328.24,5953.76 307.05,5932.57 307.05,5829.39 330.29,5806.15 485.57,5806.15 497.29,5817.87 497.29,5946.31
P5V0(m) on Top Layer "Top Layer-P5V0(m)" (solid, pour order 1118): 586.84,2116.39 568.6,2134.63 286.45,2134.63 226.08,2195.47 116.47,2195.47 96.2,2175.2 96.2,2076.86 115.61,2057.44 226.84,2057.44 264.21,2020.08 436.14,2020.08 572.09,2020.08 586.84,2034.83
NetD20_2 on Top Layer "Top Layer-NetD20_2" (solid, pour order 1124): 907.92,2025.29 899.44,2016.81 867.73,2016.81 755.82,1904.9 755.82,1773.45 749.91,1767.54 647.03,1767.54 630.76,1783.81 630.76,1857.21 645.71,1872.17 747.65,1974.11 747.65,2108.14 764.05,2124.53 900.81,2124.53 907.92,2117.42
P5V0(m,Op) on Top Layer "Top Layer-P5V0(Op) 2" (solid, pour order 924): 3139,3135 3150,3124 3150,3089 3140,3079 3026,3079 3017,3088 3017,3127 3025,3135
GND(m) on Top Layer "Top Layer-GND(m) 3" (solid, pour order 1126): 296.04,1879.28 296.04,1976.81 318.25,1999.02 489.05,1999.02 494.87,1993.2 494.86,1887.96 467.35,1860.44 314.88,1860.44
GND on Top Layer "Top Layer-GND 25" (solid, pour order 418): 2550.84,7123.74 2560.12,7114.45 2560.12,7057.04 2553.29,7050.21 2469.33,7050.21 2456.64,7062.9 2456.64,7108.49 2471.88,7123.74
P5V0(m) on Top Layer "Top Layer-P5V0 2" (solid, pour order 1128): 469.75,468.55 469.75,570.19 445.87,594.07 383.58,594.07 374.66,602.99 374.66,659.09 390.49,674.92 551.55,674.92 569.5,656.97 569.5,469.48 553.77,453.76 484.53,453.76
NetC104_1 on Top Layer "Top Layer-NetC44_1" (solid, pour order 840): 29 vertices, not listed, extent 982.23,802.47 1602.23,1195.06
P5V0 on Top Layer "Top Layer-P5V0 1" (solid, pour order 1130): 239.93,6128.08 289.71,6078.3 570.04,6078.3 592.18,6056.16 592.18,5985.29 576.52,5969.64 255.44,5969.64 220.29,6004.8 122.35,6004.8 107.34,6019.8 107.34,6115.68 119.74,6128.08
P3V3(b) on Top Layer "Top Layer-P3V3(b) 1" (solid, pour order 1134): 1227.99,6999.86 1203.3,6975.17 1203.3,6875.15 1227.99,6850.46 1331.82,6850.46 1345.11,6863.75 1345.11,6946.05 1364.73,6965.67 1455.89,6965.67 1462.86,6972.64 1462.86,6992.26 1455.26,6999.86
NetC12_1 on Top Layer "Top Layer-NetC11_1" (solid, pour order 1140): 1081.32,7348.4 1091.11,7338.61 1091.11,7185.69 1079.49,7174.07 803.61,7174.07 767.05,7210.63 767.05,7285.42 830.03,7348.4
GND on Top Layer "Top Layer-GND 13" (solid, pour order 1148): 17 vertices, not listed, extent 528.62,7189.28 1093.91,7675.56
Vcc(y) on Top Layer "Top Layer-Vcc(y) 1" (solid, pour order 1150): 1499.98,5766.46 1499.98,5581.68 1523.1,5558.55 1580.8,5558.55 1595.99,5573.75 1595.99,5764.85 1583,5777.85 1511.36,5777.85
GND on Top Layer "Top Layer-GND 20" (solid, pour order 428): 3270.74,4721.13 3303.87,4688 3360.96,4688 3379.74,4706.78 3379.74,4885.12 3354.11,4910.75 3291.28,4910.75 3270.74,4890.21
NetR261_1 on Top Layer "Top Layer-NetR134_1" (solid, pour order 874): 2342.1,695.19 2356.75,680.55 2356.74,588.55 2339.98,571.78 2252.51,571.78 2214.75,609.55 2152.75,609.55 2136.75,625.55 2136.75,684.08 2147.86,695.19
P3V3(b) on Top Layer "Top Layer-P3V3(b)" (solid, pour order 1144): 1119.82,7177.68 1220.6,7177.68 1236.59,7193.66 1236.59,7243.75 1220.52,7259.82 1118.85,7259.82 1110.54,7251.51 1110.54,7186.96
GND(m) on Top Layer "GND-GND(m)" (solid, pour order 1156): 31.59,3794.49 78.99,3841.9 3850.17,3841.9 3888.15,3803.92 3888.15,78.88 3835.72,26.45 62.11,26.45 31.59,56.97
Vcc on Bottom Layer "Bottom Layer-Vcc 1" (solid, pour order 644): 2510.87,4982.31 2489.76,4961.75 2377.52,4961.75 2362.01,4977.25 2362.01,5029.22 2430.84,5098.04 2430.84,5543.84 2441.56,5554.56 2502.16,5554.56 2510.87,5545.85
P3V3 on Bottom Layer "Bottom Layer-P3V3" (solid, pour order 646): 1787,7279 1805.09,7260.91 1875.43,7260.91 1889.16,7274.64 1889.16,7384.03 1867,7406.2 1867,7474.19 1860.63,7480.56 1794.01,7480.56 1787,7473.55
P3V3 on Bottom Layer "Bottom Layer-P3V3 2" (solid, pour order 648): 619.5,7018.91 531.44,7018.91 504.59,6992.89 504.59,6786.13 515.54,6775.18 578.88,6775.19 591.47,6787.78 591.47,6884.61 634.24,6927.38 634.24,7004.16
GND on Bottom Layer "Bottom Layer-GND 7" (solid, pour order 650): 3269.55,6937.8 3400.4,6937.8 3429.9,6967.3 3429.9,7093.03 3409.72,7113.22 3273.31,7113.22 3258.09,7097.34 3258.09,6949.26
P5V0 on Bottom Layer "Bottom Layer-P5V0" (solid, pour order 652): 485.63,4221.93 492.46,4228.75 543.96,4228.75 601.66,4228.75 610.06,4220.35 610.06,4163.78 601.81,4155.53 583.08,4155.53 568.14,4170.47 488.09,4170.47 485.63,4172.92 485.63,4205.47
P5V0 on Bottom Layer "Bottom Layer-P5V0 2" (solid, pour order 654): 2602.13,4210.78 2611.08,4219.73 3054.04,4219.73 3062.08,4211.7 3062.08,4146.19 3054.69,4138.8 2609.82,4138.8 2602.13,4146.49
P5V0 on Bottom Layer "Bottom Layer-P5V0 3" (solid, pour order 656): 2844.95,5566.12 2844.95,5456.28 2852.33,5448.9 2918.66,5448.9 2926.17,5456.4 2926.17,5573.09 2919.61,5579.65 2879.42,5579.65 2850.79,5579.65 2844.94,5573.79
P5V0(Op) on Bottom Layer "Bottom Layer-P5V0(Op)" (solid, pour order 660): 1106.86,4515.86 1106.86,4521.85 1112.04,4527.03 1274.2,4527.03 1279.79,4521.44 1279.79,4438.17 1273.89,4432.26 1111.07,4432.26 1106.48,4436.85
Vcc on Bottom Layer "Bottom Layer-Vcc" (solid, pour order 664): 2837,6021 2827,6011 2827,5952 2837.01,5941.99 2926.67,5941.99 2936.08,5951.4 2936.08,6010.53 2925.61,6021
GND on Bottom Layer "Bottom Layer-GND" (solid, pour order 666): 2344.3,5548.11 2409.18,5548.11 2417.3,5539.98 2417.3,5429.63 2400.3,5412.63 2351.41,5412.63 2333.3,5430.75 2333.3,5537.11
GND on Bottom Layer "Bottom Layer-GND 1" (solid, pour order 668): 2544,5548.47 2608.87,5548.47 2617,5540.35 2617,5430 2600,5413 2551.11,5413 2533,5431.11 2533,5537.47
P5V0 on Bottom Layer "Bottom Layer-P5V0 1" (solid, pour order 670): 3395,6921 3403,6913 3403,6848 3392,6837 3272.28,6837 3256,6853.28 3256,6911 3266,6921
Vcc(z) on Bottom Layer "Bottom Layer-Vcc(z)" (solid, pour order 674): 1831,5893 1838,5886 1838,5733 1826,5721 1725,5721 1708,5738 1708,5878 1723,5893
Vee(x) on Bottom Layer "Bottom Layer-Vee(x)" (solid, pour order 676): 1746.29,5330.29 1718,5302 1718,5185 1743,5160 1821,5160 1838,5177 1838,5321 1828.71,5330.29
NetC66_2 on Bottom Layer "Bottom Layer-NetC66_2" (solid, pour order 684): 2392.07,4470.91 2384.5,4463.34 2384.5,4431.46 2384.32,4392.01 2348,4355.69 2276.85,4355.69 2266.47,4345.31 2266.47,4239.06 2276.8,4228.73 2429.09,4228.73 2450.93,4250.58 2450.93,4460.03 2440.05,4470.9
NetC63_1 on Bottom Layer "Bottom Layer-NetC63_1" (solid, pour order 690): 2535.5,4246 2544,4254.5 2544,4713 2494,4763 2412,4763 2390,4741 2390,4699 2412,4677 2454,4677 2465,4666 2465,4270 2489,4246
NetC45_2 on Bottom Layer "Bottom Layer-NetC45_2" (solid, pour order 698): 1317.22,5003.15 1309.66,4995.58 1309.66,4963.7 1309.47,4924.25 1273.15,4887.94 1209.38,4887.94 1191.62,4870.18 1191.62,4771.31 1201.95,4760.98 1354.24,4760.98 1376.09,4782.82 1376.09,4992.27 1365.21,5003.15
NetC44_1 on Bottom Layer "Bottom Layer-NetC44_1" (solid, pour order 700): 1395,5011.99 1413.62,5030.61 1573.23,5030.61 1590,5013.84 1590,4955.99 1575.34,4941.33 1507.34,4941.33 1483,4916.99 1483,4806 1462.18,4785.18 1417.82,4785.18 1395,4808
NetC54_2 on Bottom Layer "Bottom Layer-NetC54_2" (solid, pour order 710): 1317.94,5526.31 1310.37,5518.75 1310.37,5486.86 1310.19,5447.42 1273.87,5411.1 1206.54,5411.1 1192.34,5396.89 1192.34,5294.47 1200.13,5286.68 1357.5,5286.68 1376.8,5305.98 1376.8,5515.43 1365.92,5526.31
NetC51_1 on Bottom Layer "Bottom Layer-NetC51_1" (solid, pour order 714): 1395,5517 1413.62,5535.62 1573.23,5535.62 1590,5518.85 1590,5461 1575.34,5446.34 1507.34,5446.34 1483,5422 1483,5316.06 1468.91,5301.97 1409.03,5301.97 1395,5316
P5V0(R) on Bottom Layer "Bottom Layer-P5V0(R)" (solid, pour order 658): 74 vertices, not listed, extent 920.52,5835.99 3247.18,7395.17
P3V3 on Bottom Layer "Bottom Layer-P3V3 1" (solid, pour order 662): 618.83,6475.62 643.45,6451 728,6451 741,6464 741,6510 726,6525 677.11,6525 602.91,6599.2 521.04,6599.2 510.48,6588.65 510.48,6538.38 520.03,6528.83 565.62,6528.83
P5V0(m) on Bottom Layer "Bottom Layer-P5V0 2" (solid, pour order 894): 2601.25,261.7 2610.19,270.65 3053.16,270.65 3061.2,262.61 3061.2,197.11 3053.81,189.72 2608.93,189.72 2601.25,197.4
P5V0(mR) on Bottom Layer "Bottom Layer-P5V0(mR)" (solid, pour order 920): 1649.11,2606.87 1649.11,2243.35 1474.01,2068.26 933.76,2068.26 916.17,2050.67 916.17,1917.25 942.83,1890.59 1631.83,1890.59 1837.75,2096.52 1837.75,2593.22 1793.11,2637.87 1679.11,2637.87
P3V3(m) on Bottom Layer "Bottom Layer-P3V3" (solid, pour order 940): 1784.63,3326.05 1799.37,3311.31 1878.06,3311.31 1895.44,3328.69 1895.44,3426.19 1864.63,3457.01 1864.63,3525 1858.26,3531.37 1791.64,3531.37 1784.63,3524.36
Vcc(m,x) on Bottom Layer "Bottom Layer-Vcc(x)" (solid, pour order 974): 792.99,1818.29 1422.97,1818.29 1436.75,1804.52 1436.75,1729.64 1422.76,1715.65 741.22,1715.65 533.42,1923.46 113.54,1923.46 98,1939 98,2019 120,2041 568.54,2041
P5V0(m,Op) on Bottom Layer "Bottom Layer-P5V0(Op)" (solid, pour order 1014): 1095.03,558.03 1111.04,574.03 1253.91,574.03 1268.89,559.04 1268.89,499 1249.16,479.26 1110.07,479.26 1094.73,494.6
NetC107_2 on Bottom Layer "Bottom Layer-NetC45_2" (solid, pour order 1018): 1316.22,1050.15 1308.66,1042.58 1308.66,1010.7 1308.47,971.25 1272.15,934.94 1205.53,934.94 1190.62,920.02 1190.62,818.31 1200.95,807.98 1353.24,807.98 1375.09,829.82 1375.09,1042.97 1367.91,1050.15
NetC104_1 on Bottom Layer "Bottom Layer-NetC44_1" (solid, pour order 1020): 1395.66,1049.08 1408.86,1062.28 1573.89,1062.28 1590.66,1045.51 1590.66,987.66 1576,973 1508,973 1483.66,948.66 1483.66,837.67 1462.84,816.86 1411,816.86 1395.66,832.19
NetC114_2 on Bottom Layer "Bottom Layer-NetC54_2" (solid, pour order 1026): 1319.79,1576.16 1309.37,1565.75 1309.37,1533.86 1309.19,1494.42 1272.87,1458.1 1209.1,1458.1 1191.34,1440.34 1191.34,1341.47 1201.67,1331.14 1353.96,1331.14 1375.8,1352.98 1375.8,1565.29 1364.93,1576.16
NetC111_1 on Bottom Layer "Bottom Layer-NetC51_1" (solid, pour order 1030): 1394.65,1566.68 1413.27,1585.3 1572.88,1585.3 1589.65,1568.53 1589.65,1510.68 1574.99,1496.02 1506.99,1496.02 1482.65,1471.68 1482.65,1365.74 1468.56,1351.65 1408.67,1351.65 1394.65,1365.68
NetC123_1 on Bottom Layer "Bottom Layer-NetC63_1" (solid, pour order 1032): 2535.15,295.68 2543.65,304.18 2543.65,762.68 2493.65,812.68 2411.65,812.68 2389.65,790.68 2389.65,748.68 2411.65,726.68 2453.65,726.68 2464.65,715.68 2464.65,319.68 2488.65,295.68
NetC126_2 on Bottom Layer "Bottom Layer-NetC66_2" (solid, pour order 1038): 2391.72,520.58 2384.15,513.02 2384.15,481.13 2383.97,441.69 2347.65,405.37 2283.87,405.37 2266.11,387.61 2266.11,288.74 2276.45,278.41 2428.74,278.41 2448.46,298.13 2448.46,511.82 2439.7,520.58
Vee(mx) on Bottom Layer "Bottom Layer-Vee(x)" (solid, pour order 1044): 1750.72,1384.74 1717.65,1351.68 1717.65,1234.68 1742.65,1209.68 1820.65,1209.68 1837.65,1226.68 1837.65,1370.68 1823.58,1384.74
Vcc(mz) on Bottom Layer "Bottom Layer-Vcc(z)" (solid, pour order 1046): 1830.65,1942.68 1837.65,1935.68 1837.65,1782.68 1826.65,1771.68 1725.65,1771.68 1724.65,1770.68 1707.65,1787.68 1707.65,1927.68 1722.65,1942.68
P5V0(m) on Bottom Layer "Bottom Layer-P5V0" (solid, pour order 1050): 485.28,271.6 492.11,278.43 543.6,278.43 601.3,278.42 609.7,270.02 609.7,213.45 601.45,205.2 582.72,205.2 567.78,220.14 493.59,220.14 485.28,228.45 485.28,255.15
P3V3(m) on Bottom Layer "Bottom Layer-P3V3 1" (solid, pour order 1054): 618.83,2525.62 643.45,2501 731.98,2501 742.08,2511.11 742.08,2562.82 729.9,2575 677.11,2575 602.91,2649.2 517.76,2649.2 506.43,2637.87 506.43,2587.24 518.67,2575 569.45,2575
